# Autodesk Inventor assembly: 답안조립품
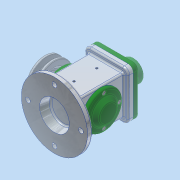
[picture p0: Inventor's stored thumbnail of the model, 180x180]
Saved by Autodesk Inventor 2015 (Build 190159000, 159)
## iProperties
Created: 2018-10
Part Number: 답안조립품
Document SubType Name: Assembly
Designer: user
Author: user
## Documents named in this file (18)
- C:\Users\user\Desktop\481007V1069\답안조립품.iam
- C:\Users\user\Desktop\481007V1069\본체.ipt
- C:\Users\user\Desktop\481007V1069\E-링.ipt
- C:\Users\user\Desktop\481007V1069\V-벨트풀리.ipt
- C:\Users\user\Desktop\481007V1069\덮개.ipt
- C:\Users\user\Desktop\481007V1069\뒤커버.ipt
- C:\Users\user\Desktop\481007V1069\링크.ipt
- C:\Users\user\Desktop\481007V1069\베어링 17 x 40 x 12.ipt
- C:\Users\user\Desktop\481007V1069\볼트 M4 x 8.ipt
- C:\Users\user\Desktop\481007V1069\볼트 M4 x 10.ipt
- C:\Users\user\Desktop\481007V1069\슬라이더.ipt
- C:\Users\user\Desktop\481007V1069\앞커버.ipt
- C:\Users\user\Desktop\481007V1069\오일 실 17 30 8.ipt
- C:\Users\user\Desktop\481007V1069\와셔 4x16.ipt
- C:\Users\user\Desktop\481007V1069\클레비스 핀 6 x 22.ipt
- 클레비스 핀 6 x 22.ipt
- C:\Users\user\Desktop\481007V1069\키 4 x 4 x 12.ipt
- C:\Users\user\Desktop\481007V1069\편심축.ipt
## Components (2 placed, 2 different names)
1. E-링:1
2. V-벨트풀리:1
